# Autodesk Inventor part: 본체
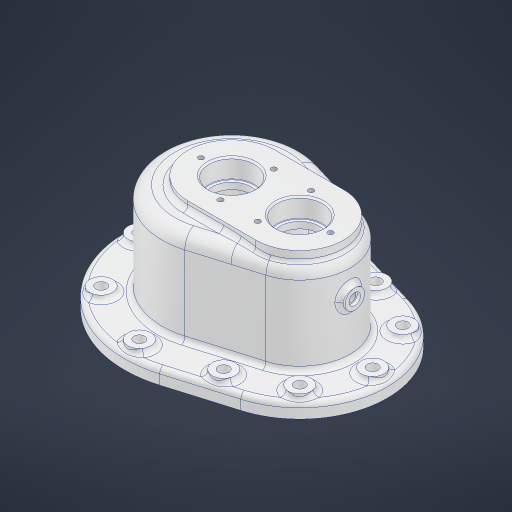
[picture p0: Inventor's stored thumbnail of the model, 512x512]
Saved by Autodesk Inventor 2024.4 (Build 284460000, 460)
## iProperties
Created: 2026-03
Part Number: 본체
Material: 알루미늄 6061
Document SubType Name: Modeling
Designer: user
Density: 2.7 g/cm^3
Appearance: 알루미늄 - 평지
Mass: 770.437 g
Surface Area: 813.797 cm^2
Volume: 285.347 cm^3
Author: user
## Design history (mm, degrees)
sketch "스케치1"
  geometry: L1 (0, 0)-(-42, 0); L2 (1.56, 69.336)-(-79.766, 45.089); L3 (-0.924, -68.595)-(-85.409, -43.407); C1 r 66 at (0, 0); C2 r 54 at (-42, 0); 5 further points
  constraints: 6 end point, 4 tangent, 2 centre point, 2 coincident, 1 horizontal
  dimensions: "d0" = 132 diameter of C1; "d1" = 42 distance of L1.start L1.end; "d2" = 108 diameter of C2
extrude "돌출1" new body sketch "스케치1" distance "d3" = 9; taper "d4" = 0 deg
sketch "스케치2"
  geometry: L1 (7.218, -42.718)-(66.311, -25.1); L2 (63.565, 25.919)-(1.425, 44.446); C1 r 43 at (0, 0); C2 r 31 at (42, 0); A1 r 54 centre (42, 0) between (57.429, -51.749) and (57.429, 51.749) reference; A2 r 66 centre (0, 0) between (18.857, 63.249) and (18.857, -63.249) reference; 4 further points
  constraints: 4 end point, 4 tangent, 2 centre point, 2 coincident
  dimensions: "d5" = 86 diameter of C1; "d6" = 62 diameter of C2
extrude "돌출2" join sketch "스케치2" distance "d7" = 57; taper "d8" = 0 deg
sketch "스케치3"
  geometry: L1 (0, -27)-(42, -27); L2 (42, 27)-(0, 27); A1 r 31 centre (42, 0) between (50.857, -29.708) and (50.857, 29.708) reference; A2 r 43 centre (0, 0) between (12.286, 41.208) and (12.286, -41.208) reference; A3 r 27 centre (0, 0) between (0, -27) and (0, 27); A4 r 27 centre (42, 0) between (42, -27) and (42, 27)
  constraints: 4 end point, 4 point on circle, 2 centre point, 2 coincident, 1 horizontal, 1 parallel, 1 tangent
  dimensions: "d9" = 54 diameter of A3; "d10" = 54 diameter of A4
extrude "돌출3" join sketch "스케치3" distance "d11" = 5; taper "d12" = 0 deg
sketch "스케치4"
  geometry: C1 r 19 at (0, 0); C2 r 19 at (42, 0); A1 r 27 centre (42, 0) between (42, -27) and (42, 27) reference; A2 r 27 centre (0, 0) between (0, 27) and (0, -27) reference; 2 further points
  constraints: 4 coincident, 2 centre point
  dimensions: "d13" = 38 diameter of C1; "d14" = 38 diameter of C2
hole "구멍1" sketch "스케치4" at (0, 0), (42, 0) diameter "d15" = 24; stored, may be unused: countersink angle "d19" = 90 deg, drill point angle "d21" = 0 deg; dims "d16" = 9, "d17" = 28, "d18" = 12, "d20" = 16
sketch "스케치5"
  geometry: L1 (-29.714, -41.208)-(8.857, -29.708) reference; L2 (8.857, 29.708)-(-29.714, 41.208) reference; L3 (-31.143, 36.416)-(7.429, 24.916); L4 (7.429, -24.916)-(-31.143, -36.416); C1 r 12 at (0, 0) reference; A1 r 43 centre (-42, 0) between (-29.714, 41.208) and (-29.714, -41.208) reference; A2 r 31 centre (0, 0) between (8.857, -29.708) and (8.857, 29.708) reference; A3 r 38 centre (-42, 0) between (-31.143, 36.416) and (-31.143, -36.416); A4 r 26 centre (0, 0) between (7.429, -24.916) and (7.429, 24.916); 1 further point
  constraints: 4 end point, 4 point on circle, 2 centre point, 3 other
  dimensions: "d22" = 5 radial gap between concentric circles of A1 A3
extrude "돌출4" cut sketch "스케치5" distance "d23" = 37; taper "d24" = 0 deg
sketch "스케치6"
  geometry: L1 (-31.143, 36.416)-(7.429, 24.916) reference; L2 (7.429, -24.916)-(-31.143, -36.416) reference; L3 (-42, 0)-(-80, 0); L4 (-18.073, 8.125)-(-90.791, 50.109); L5 (-9.415, -3.126)-(-97.468, -53.964); L6 (-72.678, -48.799)-(42.051, -14.594); L7 (58.931, 9.561)-(-31.143, 36.416); L8 (-31.143, 36.416)-(-58.069, 44.444); C1 r 19 at (-42, 0); A1 r 38 centre (-42, 0) between (-31.143, 36.416) and (-31.143, -36.416) reference; A2 r 26 centre (0, 0) between (7.429, -24.916) and (7.429, 24.916) reference; A3 r 26 centre (0, 0) between (-11.857, 23.139) and (7.429, -24.916); A4 r 38 centre (-42, 0) between (-31.143, 36.416) and (-31.143, -36.416); A5 r 38 centre (-42, 0) between (-11.857, 23.139) and (-31.143, 36.416); A6 r 26 centre (0, 0) between (7.429, 24.916) and (-11.857, 23.139); A7 r 26 centre (0, 0) between (7.429, -24.916) and (7.429, 24.916); A8 r 38 centre (-42, 0) between (-31.143, -36.416) and (-11.857, 23.139); 4 further points
  constraints: 13 end point, 13 point on circle, 13 tangent, 7 centre point, 3 coincident, 2 concentric, 2 point on line
  dimensions: "d25" = 38 diameter of C1; "d28" = 30 deg angle of L3 L4; "d29" = 60 deg angle of L5 L4
extrude "돌출5" cut sketch "스케치6" extent not by distance; stored distance "d30" = 0; taper "d31" = 0 deg
sketch "스케치7"
  geometry: L1 (57.429, 51.749)-(18.857, 63.249) reference; L2 (18.857, -63.249)-(57.429, -51.749) reference; L3 (0, 0)-(0, -57); L4 (0, 0)-(0, 57); L5 (0, 0)-(-63.062, 63.062); L6 (0, 0)-(-73.974, -73.974); L7 (18.857, -63.249)-(57.429, -51.749) reference; L8 (57.429, 51.749)-(18.857, 63.249) reference; L9 (16.286, -54.624)-(54.857, -43.124); L10 (54.857, 43.124)-(16.286, 54.624); L11 (0, 0)-(42, 0); L12 (42, 0)-(42, -67.903); L13 (42, -67.903)-(42, 86.484); L14 (42, 0)-(119.528, 0); L15 (42, 0)-(99.754, -57.754); L16 (42, 0)-(112.262, 70.262); L17 (0, 0)-(-57, 0); C1 r 12 at (0, 0) reference; C2 r 7 at (-57, 0); C3 r 7 at (-40.305, 40.305); C4 r 7 at (-40.305, -40.305); C5 r 7 at (0, 57); C6 r 7 at (0, -57); C7 r 7 at (42, -46.957); C8 r 7 at (42, 46.957); C9 r 7 at (73.82, 31.82); C10 r 7 at (87, 0); C11 r 7 at (73.82, -31.82); A1 r 54 centre (42, 0) between (57.429, -51.749) and (57.429, 51.749) reference; A2 r 45 centre (42, 0) between (87, 0) and (73.82, 31.82); A3 r 57 centre (0, 0) between (0, -57) and (0, 57); 5 further points
  constraints: 26 end point, 12 centre point, 10 coincident, 9 point on line, 8 point on circle, 3 horizontal, 2 parallel, 2 vertical
  dimensions: "d32" = 90 diameter of A2; "d33" = 114 diameter of A3; "d34" = 45 deg angle of L6 L3; "d35" = 45 deg angle of L4 L5; "d36" = 14 diameter of C2; "d37" = 14 diameter of C3; "d38" = 14 diameter of C4; "d39" = 14 diameter of C5; "d40" = 14 diameter of C6; "d41" = 9 distance between parallel lines of L2 L9; "d42" = 9 distance between parallel lines of L1 L10; "d43" = 42 distance of L11.start L11.end; "d44" = 45 deg angle of L14 L16; "d45" = 45 deg angle of L15 L14; "d46" = 14 diameter of C7; "d47" = 14 diameter of C8; "d48" = 14 diameter of C9; "d49" = 14 diameter of C10; "d50" = 14 diameter of C11; "d51" = 42 horizontal distance of point (42, -46.957) C6.centre
extrude "돌출6" join sketch "스케치7" distance "d52" = 3; taper "d53" = 0 deg
sketch "스케치8"
  geometry: C1 r 7 at (0, 0) reference; C2 r 7 at (-82.305, 6.652) reference; C3 r 7 at (-99, 46.957) reference; C4 r 7 at (-82.305, 87.263) reference; C5 r 7 at (-42, 103.957) reference; C6 r 7 at (0, 93.915) reference; C7 r 7 at (31.82, 78.777) reference; C8 r 7 at (45, 46.957) reference; C9 r 7 at (31.82, 15.138) reference; C10 r 7 at (-42, -10.043) reference; 11 further points
  constraints: 10 coincident
hole "구멍2" sketch "스케치8" at (-82.305, 6.652), (-99, 46.957), (-82.305, 87.263), (-42, 103.957), (0, 93.915), (31.82, 78.777), (45, 46.957), (31.82, 15.138), (0, 0), (-42, -10.043) diameter "d54" = 6.6; stored, may be unused: countersink angle "d58" = 90 deg, drill point angle "d60" = 0 deg; dims "d55" = 6, "d56" = 4, "d57" = 2, "d59" = 8
fillet "모깎기1" dims "d61" = 0.3
chamfer "모따기1" distance "d62" = 1; stored, may be unused: second distance "d63" = 2, angle "d64" = 45 deg
sketch "스케치9" dims "d65" = 38
  geometry: C1 r 15 at (0, 0) reference; C2 r 19 at (42, 0); A1 r 27 centre (42, 0) between (42, -27) and (42, 27) reference; 2 further points
  constraints: 2 coincident, 1 centre point, 1 horizontal alignment, 2 other
  dimensions: "d66" = 38 diameter of C2
hole "구멍3" sketch "스케치9" at (-19, 0) diameter "d67" = 3.242; stored, may be unused: countersink angle "d71" = 90 deg, drill point angle "d73" = 118 deg; dims "d68" = 8, "d69" = 4, "d70" = 2, "d72" = 10
sketch "스케치10" dims "d77" = 38
  geometry: A1 r 27 centre (42, 0) between (42, -27) and (42, 27) reference; 2 further points
  constraints: 1 coincident, 1 horizontal alignment, 2 other
hole "구멍4" sketch "스케치10" at (61, 0) diameter "d78" = 3.242; stored, may be unused: countersink angle "d82" = 90 deg, drill point angle "d84" = 118 deg; dims "d79" = 8, "d80" = 4, "d81" = 2, "d83" = 10
node "작업 평면1"
sketch "스케치11"
  geometry: L1 (0, 0)-(43, 0); C1 r 6 at (43, 0)
  constraints: 2 end point, 1 centre point, 1 coincident, 1 horizontal
  dimensions: "d89" = 43 distance of L1.start L1.end; "d90" = 12 diameter of C1
extrude "돌출7" join sketch "스케치11" stored distance "d91" = 3; taper "d92" = 0 deg
node "작업 평면2"
sketch "스케치12"
  geometry: L1 (0, 0)-(43, 0); C1 r 6 at (43, 0)
  constraints: 2 end point, 1 centre point, 1 coincident, 1 horizontal
  dimensions: "d94" = 43 distance of L1.start L1.end; "d95" = 12 diameter of C1
extrude "돌출8" join sketch "스케치12" stored distance "d96" = 10; taper "d97" = 0 deg
sketch "스케치13"
  geometry: C1 r 6 at (0, 0) reference; C2 r 3.5 at (0, 0); 2 further points
  constraints: 2 coincident, 1 centre point
  dimensions: "d98" = 7 diameter of C2
extrude "돌출9" cut sketch "스케치13" distance "d99" = 2; taper "d100" = 0 deg
sketch "스케치14"
  geometry: C1 r 6 at (0, 0) reference; C2 r 3.5 at (0, 0); 1 further point
  constraints: 1 centre point, 1 coincident
  dimensions: "d101" = 7 diameter of C2
extrude "돌출10" cut sketch "스케치14" distance "d102" = 2; taper "d103" = 0 deg
sketch "스케치15"
  geometry: C1 r 3.5 at (0, 0) reference; 2 further points
  constraints: 1 coincident
hole "구멍5" sketch "스케치15" at (0, 0) diameter "d104" = 5.1881; stored, may be unused: countersink angle "d108" = 90 deg, drill point angle "d110" = 118 deg; dims "d105" = 12, "d106" = 4, "d107" = 2, "d109" = 16
sketch "스케치16"
  geometry: C1 r 3.5 at (0, 0) reference; 2 further points
  constraints: 1 coincident
hole "구멍6" sketch "스케치16" at (0, 0) diameter "d111" = 5.1881; stored, may be unused: countersink angle "d115" = 90 deg, drill point angle "d117" = 118 deg; dims "d112" = 12, "d113" = 4, "d114" = 2, "d116" = 16
fillet "모깎기2" dims "d118" = 8
fillet "모깎기3" dims "d119" = 3
fillet "모깎기4" dims "d120" = 3
fillet "모깎기5" dims "d121" = 3
fillet "모깎기6" dims "d122" = 3
fillet "모깎기7" dims "d123" = 3
sketch "스케치17"
  geometry: C1 r 14 at (0, 0); A1 r 35 centre (0, 0) between (10, 33.541) and (10, -33.541) reference
  constraints: 1 centre point, 1 coincident
  dimensions: "d124" = 28 diameter of C1
extrude "돌출11" cut sketch "스케치17" distance "d125" = 3.65; taper "d126" = 0 deg
sketch "스케치18"
  geometry: C1 r 14 at (0, 0) reference; 1 further point
  constraints: 1 coincident
hole "구멍7" sketch "스케치18" at (0, 0) diameter "d127" = 28; stored, may be unused: countersink angle "d131" = 90 deg, drill point angle "d133" = 0 deg; dims "d128" = 12, "d129" = 29.4, "d130" = 1.35, "d132" = 9.35
sketch "스케치19"
  geometry: C1 r 14 at (0, 0) reference; C2 r 12 at (0, 0)
  constraints: 1 centre point, 1 coincident
  dimensions: "d134" = 24 diameter of C2
extrude "돌출12" cut sketch "스케치19" distance "d135" = 20; taper "d136" = 0 deg
fillet "모깎기8" dims "d137" = 0.3
chamfer "모따기2" distance "d138" = 1; stored, may be unused: second distance "d139" = 2, angle "d140" = 45 deg
sketch "스케치21"
  geometry: 1 further point
sketch "스케치23"
  geometry: L1 (66, 0)-(-66, 0) reference; 6 further points
  constraints: 2 midpoint, 1 vertical alignment, 1 other
  dimensions: "d144" = 25 distance of point (0, 25) point (0, 0)
feature "엠보싱2" sketch "스케치23" dims "d145" = 0.5, "d146" = 0
fillet "모깎기12" dims "d150" = 3
fillet "모깎기13" dims "d151" = 3
node "솔리드1"
pattern_circular "원형 패턴1" dims angle "d75" = 360 deg
pattern_circular "원형 패턴2" dims angle "d86" = 360 deg
feature "A9D066F2-1C7D-4E18-AEED-F7BC21143FA4" dims "d15" = 24, "d16" = 9, "d17" = 28, "d18" = 12, "d19" = 90 deg, "d20" = 16, "d21" = 0
other parameters: "d88" = -46, "d93" = 76
